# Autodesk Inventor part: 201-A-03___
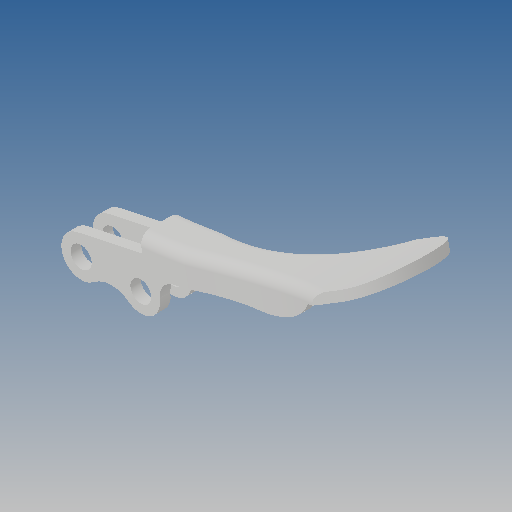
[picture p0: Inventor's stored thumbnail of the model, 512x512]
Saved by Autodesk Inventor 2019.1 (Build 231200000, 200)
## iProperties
Created: 2010-06
Part Number: 201-A-03___
Material: Ogólny
Document SubType Name: Modeling
Designer: CADENGINEERING4
Density: 1 g/cm^3
Appearance: Domyślna
Author: CADENGINEERING4
Revision Number: ANY
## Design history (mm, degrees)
feature "NONE"
node "Bryła1"
